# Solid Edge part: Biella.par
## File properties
Author: Luca
Template: Normal.par
Last saved by: Luca
Revision: 7
Application: Solid Edge
Accuracy: 0.990
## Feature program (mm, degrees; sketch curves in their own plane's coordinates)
sketch for "ExtrudedProtrusion_1" plane through (0, 0, 0) normal (0, 0, 1) x-axis (1, 0, 0)
  line (-35, 120) -> (-35, 0)
  line (35, 120) -> (35, 0)
extrude "ExtrudedProtrusion_1" add finite 10 symmetric
sketch for "unnamed Protrusion 1" #1 plane through (0, 50, 5) normal (0, 0, 1) x-axis (0, 1, 0)
  circle centre (70, 0) radius 18
sketch for "unnamed Protrusion 1" #2 plane through (0, 50, 5) normal (0, 0, 1) x-axis (0, 1, 0)
  circle centre (-50, 0) radius 22.5
extrude "unnamed Protrusion 1" add finite 2.5 along +normal
mirror "unnamed Mirror 1" of "unnamed Protrusion 1" about plane through (0, 0, 0) normal (0, 0, 1)
extrude "unnamed Protrusion 2" add finite 2.5
sketch for "unnamed Cutout 1" #1 plane through (0, 0, 0) normal (0, 0, 1) x-axis (1, 0, 0)
  circle centre (0, 0) radius 17.5
sketch for "unnamed Cutout 1" #2 plane through (0, 0, 0) normal (0, 0, 1) x-axis (1, 0, 0)
  circle centre (0, 120) radius 15
extrude "unnamed Cutout 1" cut through
sketch for "unnamed Cutout 2" plane through (0, 50, 5) normal (0, 0, 1) x-axis (0, 1, 0)
  line (56.3144, -17) -> (-13.6856, -17)
  arc centre (-13.6856, -30.7189) radius 13.7189 from (-13.6856, -17) to (-26.1556, -25) ccw
  line (-66.1556, -25) -> (-26.1556, -25)
  line (-66.1556, -25) -> (-66.1556, -20)
  arc centre (-50.0003, 0) radius 25.7098 from (-66.1556, 20) to (-66.1556, -20) ccw
  line (-66.1556, 25) -> (-66.1556, 20)
  line (-66.1556, 25) -> (-26.1556, 25)
  arc centre (-13.6856, 30.7189) radius 13.7189 from (-13.6856, 17) to (-26.1556, 25) cw
  line (56.3144, 17) -> (-13.6856, 17)
  arc centre (70, 0) radius 21.8242 from (56.3144, 17) to (56.3144, -17) cw
extrude "unnamed Cutout 2" cut through along -normal
sketch for "ExtrudedCutout_6" #1 plane through (0, 0, 0) normal (0, 0, 1) x-axis (1, 0, 0)
  circle centre (-40, 65) radius 35
sketch for "ExtrudedCutout_6" #2 plane through (0, 0, 0) normal (0, 0, 1) x-axis (1, 0, 0)
  circle centre (40, 65) radius 35
extrude "ExtrudedCutout_6" cut finite 6 symmetric
sketch for "v_4" plane through (26.0689, -16.1556, 0) normal (0, -1, 0) x-axis (-1, 0, 0)
  hole centre (4.1625, 0) bore radius 2
hole "v_4" diameter 4 through
mirror "unnamed Mirror 2" of "v_4" about plane through (0, 0, 0) normal (1, 0, 0)
hole "unnamed Hole 1" through
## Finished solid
Body 1: solid body, 32 faces, 64 edges, 32 vertices.
  Faces by surface: plane 18, cylinder 14
  Edges by curve: line 34, circle 28, intersection 2
Bounding box of the edges (mm): 50.000 x 167.534 x 15.000, from (-25, -25.7101, -7.5) to (25, 141.8242, 7.5).
Cylindrical faces by radius (mm): R2 x2, R13.7189 x2, R15 x1, R17.5 x1, R18 x2, R21.8242 x1, R22.5 x2, R25.7098 x1, R35 x2
Planar faces by outward normal: +x 2, +y 2, +z 5, -x 2, -y 2, -z 5
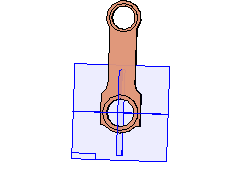
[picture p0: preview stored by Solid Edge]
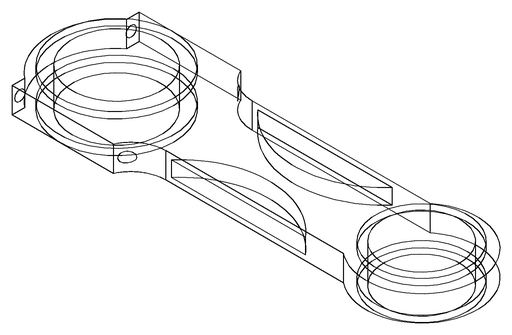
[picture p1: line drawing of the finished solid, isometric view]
